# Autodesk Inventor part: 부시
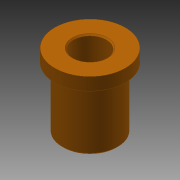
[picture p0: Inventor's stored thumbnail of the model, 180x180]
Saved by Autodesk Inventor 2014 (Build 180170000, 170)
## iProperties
Company: 한국ATC센터
Created: 2015-11
Part Number: 부시
Document SubType Name: Modeling
Designer: mdu
Density: 7.86 g/cm^3
Material: 강철, 연강
Mass: 65.5031 g
Surface Area: 42.0516 cm^2
Volume: 8.33373 cm^3
Appearance: 주황색
Author: mdu
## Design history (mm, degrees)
sketch "스케치1"
  geometry: C1 r 11 at (0, 0) reference; C2 r 14 at (0, 0) reference; C3 r 11 at (0, 0) reference; 1 further point
  node "참조1"
  node "참조2"
extrude "돌출1" new body sketch "스케치1" distance "d0" = 5; taper "d1" = 0 deg
extrude "돌출2" join sketch "스케치1" distance "d2" = 24; taper "d3" = 0 deg
hole "구멍1" diameter "d6" = 13; stored, may be unused: countersink angle "d10" = 90 deg, drill point angle "d12" = 118 deg; dims "d4" = 10, "d5" = 10, "d7" = 6, "d8" = 4, "d9" = 2, "d11" = 8
chamfer "모따기1" distance "d13" = 0.5; stored, may be unused: second distance "d14" = 2, angle "d15" = 45 deg
chamfer "모따기2" distance "d16" = 0.5; stored, may be unused: second distance "d17" = 2, angle "d18" = 45 deg
node "솔리드1"
